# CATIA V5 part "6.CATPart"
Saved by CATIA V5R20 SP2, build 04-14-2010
Part number: 6
Bounding box of the stored display mesh (mm): x -65 to 65, y -331.528 to 190, z -330 to 65
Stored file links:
  C:\Users\Orange\Desktop\Assembly Design-14\6.CATPart
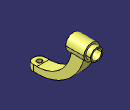
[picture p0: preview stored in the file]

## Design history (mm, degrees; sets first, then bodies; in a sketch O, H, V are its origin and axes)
Body1 (main body)
  Sketch1 on zx-plane, origin (0, 0, 0), H (-1, 0, 0), V (0, 0, 1)
    circle A1 centre (0, 0) radius 65
    circle A2 centre (0, 0) radius 50
    circle A3 centre (0, 0) radius 40
  MultiPad1: profile Sketch1, domains (length 0; length 190; length 150)
  Sketch2 on yz-plane, origin (0, 0, 0), H (0, 1, 0), V (0, 0, 1)
    point P1 (0, -330)
    arc A1 centre (-251.5302, 70) radius 400 from (-251.5302, -330) to (132.4698, -42) ccw
    arc A2 centre (-253.7785, 8.2265) radius 288.2353 from (-251.5302, -280) to (30.0469, -42) ccw
    line L1 (-251.5302, -280) -> (-331.5278, -280.624)
    line L2 (-251.5302, -330) -> (-331.5302, -330)
    line L3 (-331.5278, -280.624) -> (-331.5302, -330)
    line L4 (30.0469, -42) -> (132.4698, -42)
  Sketch3 on zx-plane, origin (0, 0, 0), H (-1, 0, 0), V (0, 0, 1)
    point P1 (1.0056, -53.9945)
    point P2 (0, -53.9945)
  Pad1: profile Sketch2, direction (1, 0, 0), length 50, mirrored extent
  DatumSurface1
  Sketch4 on face of Pad1 from Sketch2.L1, origin (0, 2.1687, -278.021), H (1, 0, 0), V (0, 1, 0.0078)
    arc A1 centre (0, -283.7066) radius 50 from (-50, -283.7066) to (50, -283.7066) ccw
    circle A2 centre (0, -283.7066) radius 20
    line L1 (50, -283.7066) -> (167.557, -283.7066)
    line L2 (167.557, -283.7066) -> (-44.1021, -422.5593)
    line L3 (-44.1021, -422.5593) -> (-110.1517, -303.528)
    line L4 (-110.1517, -303.528) -> (-50, -283.7066)
  MultiPocket1: profile Sketch4, domains (length 1000; length 2000)
  DatumCurve1
  Sketch5 on face of DatumSurface1, origin (0, 0, -380), H (1, 0, 0), V (0, 1, 0)
    projected circle E1 centre (0, -281.1446) radius 20 from edge of DatumCurve1
  Pocket1: profile Sketch5, direction (0, 0, 1), up to face of Pad1 from Sketch2.L1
